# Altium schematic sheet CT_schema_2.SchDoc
size 517 x 507 mm
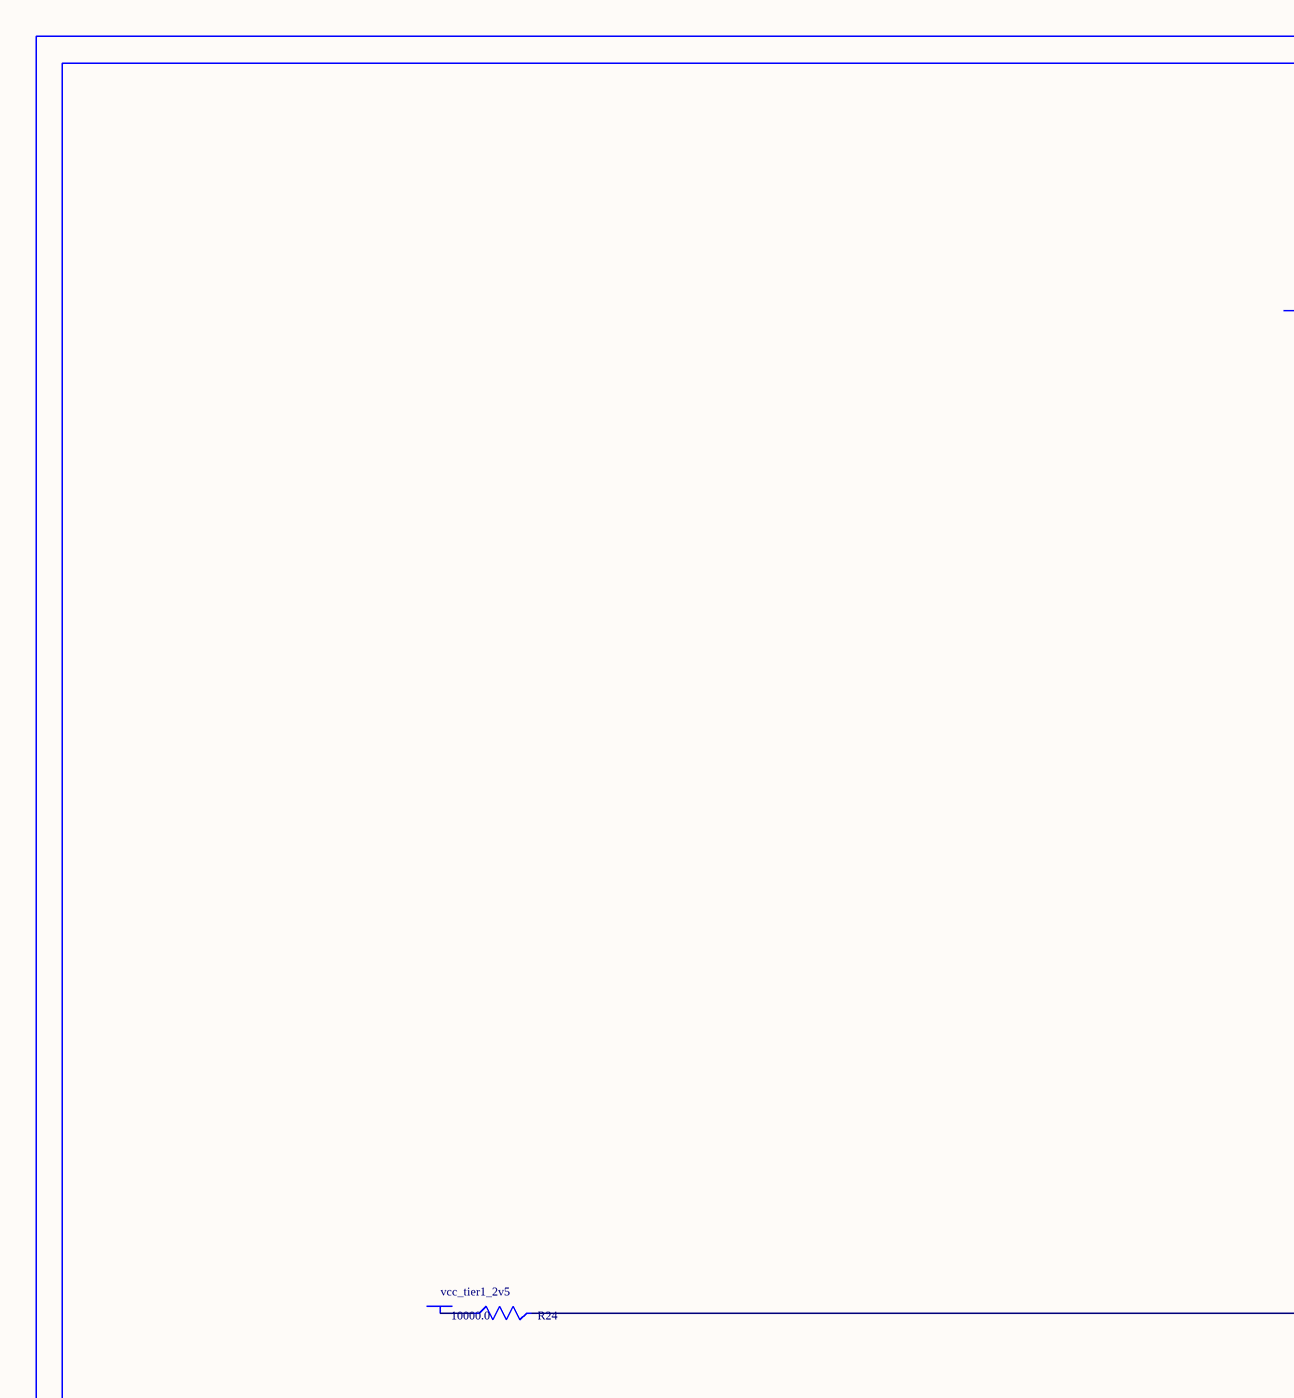
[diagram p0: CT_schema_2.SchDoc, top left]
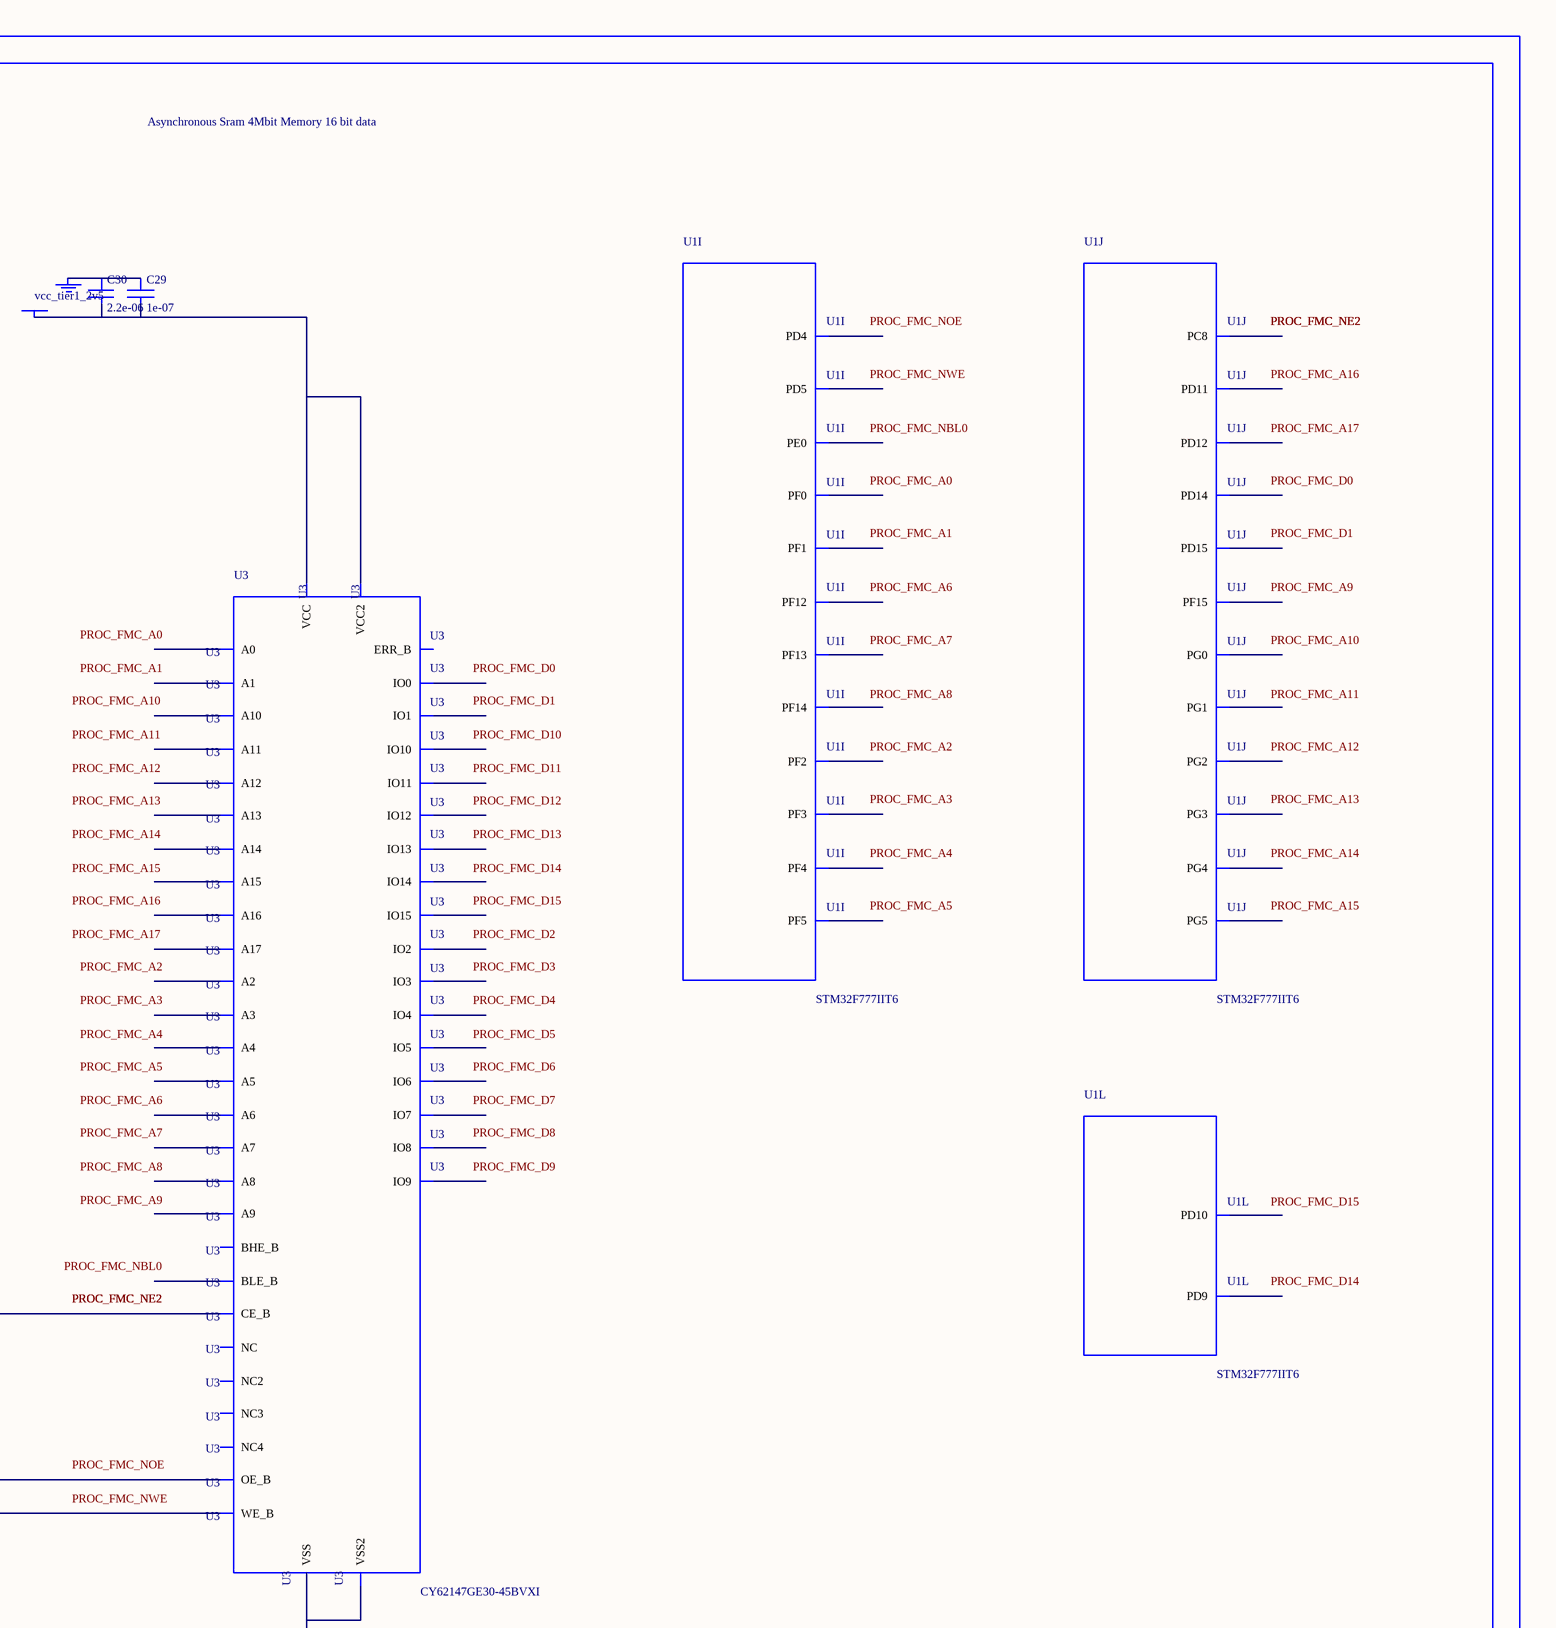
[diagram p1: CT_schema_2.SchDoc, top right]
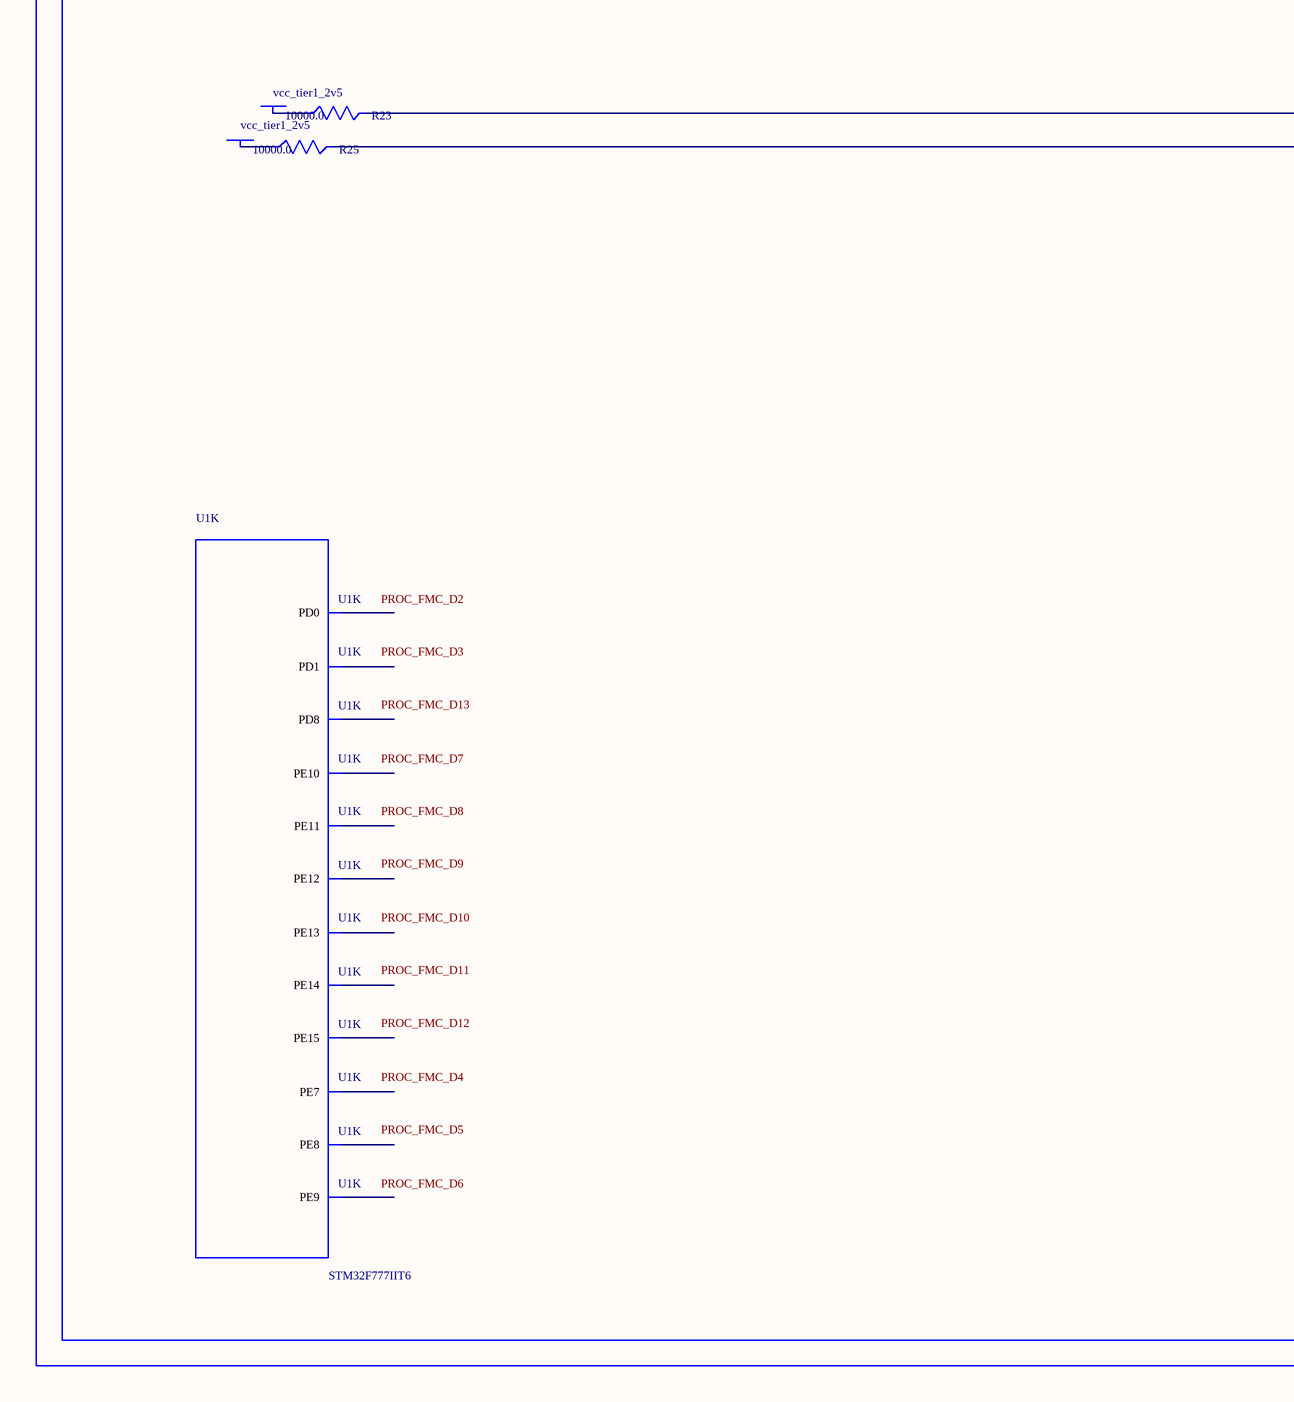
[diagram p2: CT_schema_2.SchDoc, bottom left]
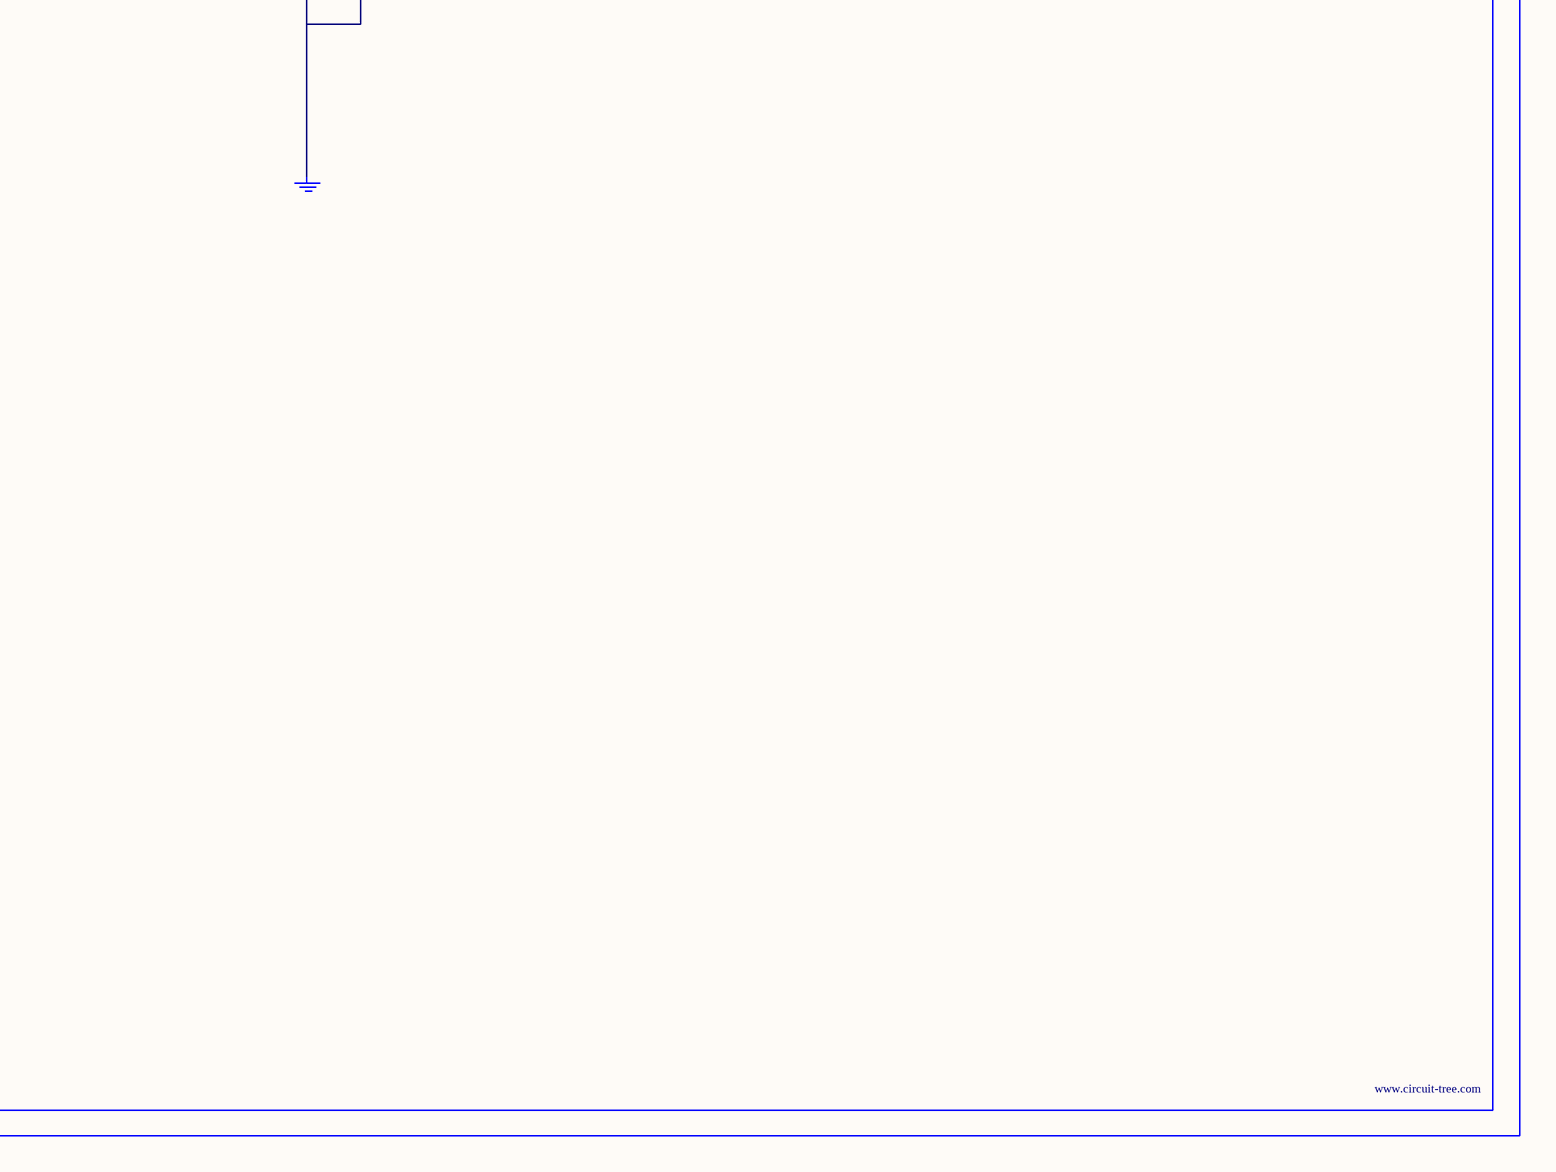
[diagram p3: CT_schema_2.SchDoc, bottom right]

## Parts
BORDER1  (no value)
C29  1e-07  [C0402]
C30  2.2e-06  [C0603]
GND_INSTANCE_1_0  (no value)
GND_INSTANCE_1_1  (no value)
POWER_INSTANCE_1_0  vcc_tier1_2v5
POWER_INSTANCE_1_1  vcc_tier1_2v5
POWER_INSTANCE_1_2  vcc_tier1_2v5
POWER_INSTANCE_1_3  vcc_tier1_2v5
R23  10000.0  [R0603]
R24  10000.0  [R0603]
R25  10000.0  [R0603]
U1  STM32F777IIT6  [LQFP176]  (parts I,J,K,L of 15)
U3  CY62147GE30-45BVXI  [VFBGA48]

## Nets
NetC29_1: C29.1 C30.1 GND_INSTANCE_1_0.0(GND)
NetC29_2: C29.2 C30.2 POWER_INSTANCE_1_0.0(PWR) U3.D6(VCC) U3.E1(VCC2)
NetGND_INSTANCE_1_1_0: GND_INSTANCE_1_1.0(GND) U3.D1(VSS) U3.E6(VSS2)
NetPOWER_INSTANCE_1_1_0: POWER_INSTANCE_1_1.0(PWR) R23.1
NetPOWER_INSTANCE_1_2_0: POWER_INSTANCE_1_2.0(PWR) R24.1
NetPOWER_INSTANCE_1_3_0: POWER_INSTANCE_1_3.0(PWR) R25.1
NetR23_2: R23.2 U3.A2(OE_B)
NetR24_2: R24.2 U3.B5(CE_B)
NetR25_2: R25.2 U3.G5(WE_B)

Not connected (* = marked no-connect by the designer): U1 16(PF0) 17(PF1) 18(PF2) 19(PF3) 20(PF4) 21(PF5) 60(PF12) 63(PF13) 64(PF14) 65(PF15) 66(PG0) 67(PG1) 68(PE7) 69(PE8) 70(PE9) 73(PE10) 74(PE11) 75(PE12) 76(PE13) 77(PE14) 78(PE15) 96(PD8) 97(PD9) 98(PD10) 99(PD11) 100(PD12) 104(PD14) 105(PD15) 106(PG2) 107(PG3) 108(PG4) 109(PG5) 117(PC8) 142(PD0) 143(PD1) 146(PD4) 147(PD5) 169(PE0); U3 A1(BLE_B) A3(A0) A4(A1) A5(A2) A6(NC) B1(IO8) B2(BHE_B) B3(A3) B4(A4) B6(IO0) C1(IO9) C2(IO10) C3(A5) C4(A6) C5(IO1) C6(IO2) D2(IO11) D3(A17) D4(A7) D5(IO3) E2(IO12) E3(ERR_B) E4(A16) E5(IO4) F1(IO14) F2(IO13) F3(A14) F4(A15) F5(IO5) F6(IO6) G1(IO15) G2(NC2) G3(A12) G4(A13) G6(IO7) H1(NC3) H2(A8) H3(A9) H4(A10) H5(A11) H6(NC4)

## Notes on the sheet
- Labels drawn without touching a wire or pin: PROC_FMC_A0, PROC_FMC_A1, PROC_FMC_A2, PROC_FMC_A3, PROC_FMC_A4, PROC_FMC_A5, PROC_FMC_A6, PROC_FMC_A7, PROC_FMC_A8, PROC_FMC_A9, PROC_FMC_A10, PROC_FMC_A11, PROC_FMC_A12, PROC_FMC_A13, PROC_FMC_A14, PROC_FMC_A15, PROC_FMC_A16, PROC_FMC_A17, PROC_FMC_D0, PROC_FMC_D1, PROC_FMC_D2, PROC_FMC_D3, PROC_FMC_D4, PROC_FMC_D5, PROC_FMC_D6, PROC_FMC_D7, PROC_FMC_D8, PROC_FMC_D9, PROC_FMC_D10, PROC_FMC_D11, PROC_FMC_D12, PROC_FMC_D13, PROC_FMC_D14, PROC_FMC_D15, PROC_FMC_NBL0, PROC_FMC_NOE, PROC_FMC_NWE

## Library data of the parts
BORDER1 = BORDER_PAGE1
C29 = C0402C104K3RACTU
C30 = C0603C225K8RACTU
GND_INSTANCE_1_0 GND_INSTANCE_1_1 = GND
POWER_INSTANCE_1_0-POWER_INSTANCE_1_3 = PWR
R23-R25 = RC0603JR-0710KL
